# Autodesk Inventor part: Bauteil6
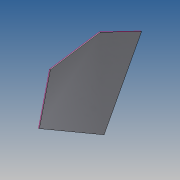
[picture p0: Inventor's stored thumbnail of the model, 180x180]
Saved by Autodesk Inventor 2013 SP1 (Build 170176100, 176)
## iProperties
Company: Kirow Ardelt GmbH
Created: 2013-01
Part Number: Bauteil6
Material: Stahl
Document SubType Name: Blech
Designer: Winkelmann
Density: 7.85 g/cm^3
Sheet Metal Rule: Standard (Ardelt)
Mass: 4629.53 g
Surface Area: 1563.88 cm^2
Volume: 589.749 cm^3
Author: Winkelmann
Revision Number: A
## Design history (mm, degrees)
derived "Bauteil4.ipt"
  sketch "Skizze1"
    geometry: L1 (-318.13, 206.345)-(86.584, 266.588) reference; L2 (86.584, 266.588)-(420.194, 105.525) reference; L3 (420.194, 105.525)-(116.643, -467.157) reference; L4 (116.643, -467.157)-(-406.665, -162.026) reference; L5 (-406.665, -162.026)-(-318.13, 206.345) reference; 1 further point
feature "Volumenkörper1::Bauteil4.ipt"
tag "Bezeichnung1"
node "Volumenkörper1"
other parameters: "Stärke" = 8 (derived), "KFaktor" = 4.4, "Biegeradius" = 8 (= Stärke), "BreiteBiegungsfreistellung" = 8 (= Stärke), "TiefeBiegungsfreistellung" = 4 (= 0.5 x Stärke), "GrößeEckenfreistellung" = 32 (= 4 x Stärke), "AbstandVerbindung" = 0.01, "MinimalRest" = 16 (= 2 x Stärke), "Übergangsradius" = 8 (= Biegeradius), "JacobiRadiusGröße" = 8 (= Biegeradius), "Abstandsgröße" = 8 (= Stärke), "Stärke_1" = 8, "Biegeradius_1" = 8, "BreiteBiegungsfreistellung_1" = 8, "TiefeBiegungsfreistellung_1" = 4, "GrößeEckenfreistellung_1" = 32, "MinimalRest_1" = 16, "Übergangsradius_1" = 8, "JacobiRadiusGröße_1" = 8, "Abstandsgröße_1" = 8, "d0_1" = 8
